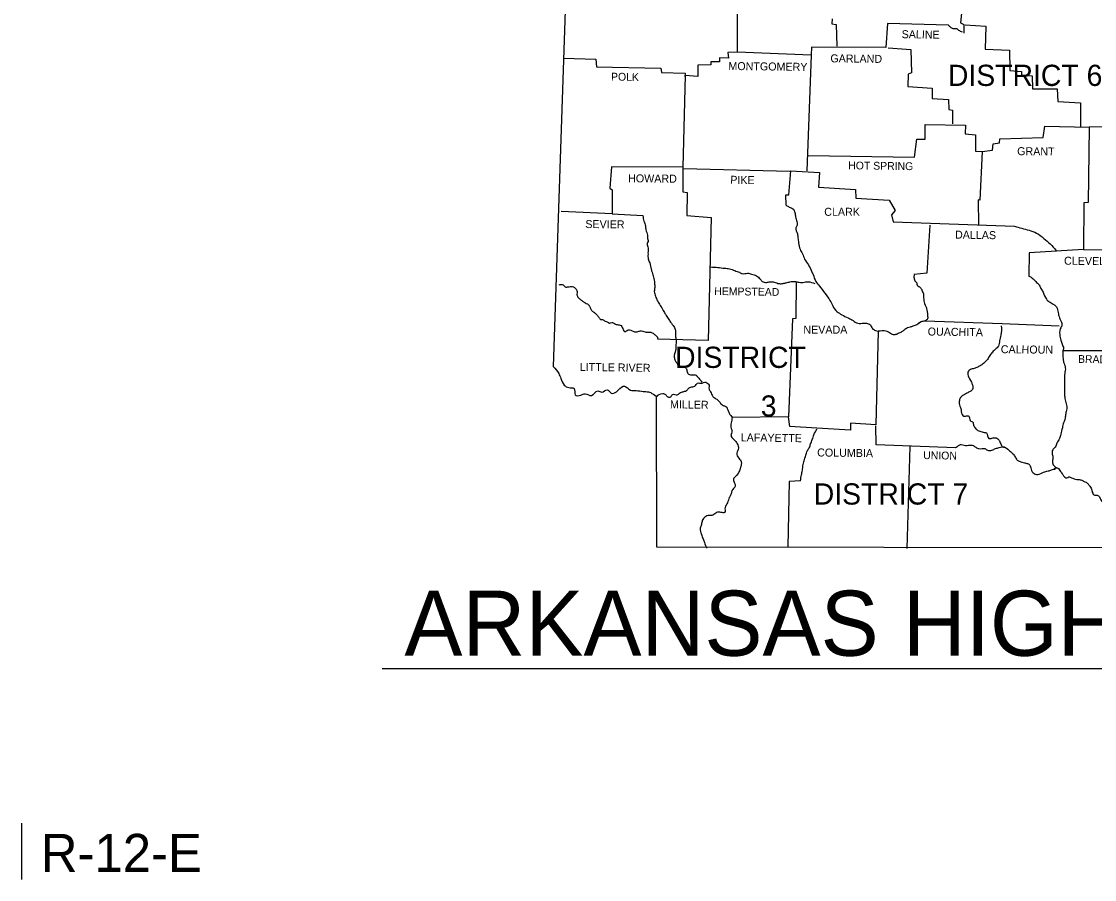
# Model space of a CAD drawing. Extents: x 171 to 3403, y 68 to 2102.
# Drawn here: x 2435 to 3000, y 1174 to 1625 of the extents above; entities that cross this region are included whole.
import ezdxf

# ---------------------------------------------------------------- set-up
doc = ezdxf.new("R2010")
doc.units = 0
for name, color, linetype in [('1', 7, 'Continuous'), ('2', 7, 'Continuous'), ('3', 7, 'Continuous'), ('Default', 7, 'Continuous')]:
    doc.layers.add(name, color=color, linetype=linetype)

msp = doc.modelspace()

# ---------------------------------------------------------------- linework, layer by layer
at = {"layer": '1'}
msp.add_line((2625.16, 1284.87), (3289.7, 1284.87), dxfattribs=at)
for points in [[(2703.71, 1871.91), (2723.96, 1709.3), (2715.15, 1443.86)], [(2812.02, 1666.35), (2811.82, 1609.11), (2806.93, 1609.01), (2807.32, 1606.08), (2802.62, 1606.17), (2802.53, 1604.02), (2797.93, 1604.02), (2798.03, 1602.46), (2791.18, 1602.26), (2791.08, 1596.29), (2784.43, 1596.88), (2783.35, 1548.74), (2745.68, 1548.84), (2744.8, 1537.69), (2746.17, 1536.71), (2746.07, 1524.18), (2719.36, 1525.36)], [(2961.91, 1638.27), (2954.86, 1639.05), (2955.16, 1636.41), (2942.34, 1635.92), (2941.95, 1632.1), (2929.91, 1631.42), (2929.23, 1624.57), (2930.99, 1623.69), (2930.99, 1619.19)], [(2861.72, 1626.72), (2861.62, 1624.08), (2863.87, 1623.69), (2864.26, 1612.34)], [(2922.97, 1623.3), (2890.97, 1624.27), (2890.09, 1611.65), (2850.96, 1611.85), (2850.76, 1607.64)], [(2931.68, 1623.59), (2942.63, 1622.9), (2942.24, 1610.67), (2955.06, 1610.19), (2955.26, 1599.52), (2961.32, 1599.03), (2961.32, 1597.17), (2967, 1596.78), (2967.19, 1589.93), (2980.11, 1589.93), (2980.5, 1583.18), (2992.44, 1582.59), (2992.34, 1569.87)], [(2850.76, 1607.64), (2811.82, 1609.11)], [(2891.27, 1611.46), (2903.11, 1610.58), (2903.5, 1598.25), (2901.83, 1597.66), (2901.64, 1591.11), (2914.46, 1590.23), (2914.46, 1584.84), (2922.97, 1584.36), (2923.07, 1578.97), (2925.12, 1578.68), (2925.02, 1571.44)], [(2720.54, 1606.08), (2737.46, 1605.49), (2737.85, 1601.38), (2771.71, 1600.69), (2772.1, 1598.54), (2784.43, 1598.15), (2784.33, 1596.29)], [(2850.76, 1607.64), (2848.51, 1546.69)], [(3109.06, 1581.13), (3072.08, 1582.1), (3071.88, 1570.07), (2997.03, 1569.78)], [(2849.2, 1554.81), (2905.16, 1554.02), (2906.24, 1563.32), (2910.64, 1563.32), (2910.74, 1571.15), (2931.87, 1570.85), (2931.68, 1566.16), (2937.16, 1565.77), (2937.16, 1557.16), (2940.68, 1556.86)], [(2940.68, 1556.86), (2946.16, 1557.64), (2946.55, 1560.97), (2949.78, 1561.56), (2949.97, 1563.52), (2972.77, 1564.2), (2973.65, 1570.17), (2997.03, 1569.78)], [(2997.03, 1569.58), (2996.45, 1530.05), (2994.2, 1529.96), (2993.9, 1505.4)], [(2940.68, 1556.86), (2939.5, 1531.23), (2938.62, 1531.52), (2938.72, 1518.22)], [(2783.35, 1548.74), (2783.35, 1535.73), (2785.5, 1535.34), (2785.31, 1523.2), (2798.22, 1522.23), (2796.66, 1457.55), (2770.04, 1458.24)], [(2783.55, 1548.06), (2839.51, 1546.59)], [(2837.65, 1528.68), (2837.46, 1534.07), (2839.02, 1534.16), (2840, 1546.78), (2855.07, 1545.81), (2854.68, 1538.08), (2874.15, 1537), (2874.24, 1532.3), (2891.85, 1531.23), (2894.89, 1525.94), (2893.03, 1523.6), (2893.91, 1519.98), (2957.7, 1517.63)], [(2746.07, 1524.18), (2762.31, 1523.2)], [(2913.09, 1518.12), (2911.62, 1492.97), (2904.87, 1492.19)], [(2979.81, 1504.52), (2965.33, 1503.64), (2965.24, 1491.41)], [(2993.9, 1505.4), (2979.62, 1504.52)], [(2993.9, 1505.4), (3028.54, 1505.2)], [(2842.84, 1488.47), (2842.64, 1469), (2840.88, 1468.81), (2838.92, 1417.24)], [(2910.64, 1467.83), (2951.15, 1466.36), (2981.18, 1465.19)], [(2885.98, 1462.35), (2884.71, 1413.04), (2871.5, 1413.92), (2871.41, 1410.3), (2853.79, 1411.37)], [(2983.14, 1452.17), (3027.36, 1452.27)], [(2769.26, 1428.1), (2769.46, 1348.95), (3128.04, 1348.36)], [(2853.79, 1411.37), (2839.61, 1412.16), (2838.92, 1417.24), (2809.28, 1416.95)], [(2926.69, 1401.1), (2884.91, 1402.67), (2884.71, 1412.55)], [(2902.72, 1401.78), (2901.15, 1348.07)], [(2845.18, 1383.68), (2839.12, 1383.29), (2838.43, 1348.85)]]:
    msp.add_lwpolyline(points, dxfattribs=at)
for points in [[(2930.31, 1619.68), (2928.45, 1620.65), (2926.98, 1621.53), (2925.41, 1621.44), (2924.14, 1622.22), (2922.97, 1623.3)], [(2837.65, 1528.68), (2839.22, 1527.71), (2841.08, 1526.83), (2842.05, 1525.36), (2842.45, 1523.11), (2843.13, 1520.66), (2843.33, 1518.12), (2842.74, 1516.75), (2843.52, 1513.62), (2843.82, 1511.46), (2844.11, 1508.92), (2844.89, 1505.5), (2846.16, 1503.15), (2847.34, 1500.31), (2849.29, 1497.28), (2850.96, 1493.95), (2851.74, 1492.19), (2853.21, 1488.57), (2855.07, 1486.12), (2858, 1482.41), (2860.64, 1478.59), (2862.11, 1475.75), (2864.36, 1472.62), (2866.91, 1471.06), (2870.13, 1469.39), (2872.19, 1468.41), (2874.54, 1466.75), (2877.57, 1466.56), (2879.82, 1466.56), (2881.88, 1465.67), (2882.85, 1463.91), (2884.61, 1462.74), (2885.98, 1462.35)], [(2762.31, 1523.2), (2762.8, 1520.27), (2763.68, 1517.73), (2763.78, 1515.77), (2764.66, 1512.83), (2764.66, 1511.76), (2764.96, 1509.61), (2764.56, 1508.43), (2765.05, 1506.08), (2764.96, 1504.32), (2764.96, 1502.85), (2765.05, 1500.41), (2765.84, 1498.26), (2766.62, 1495.03), (2767.11, 1493.36), (2767.89, 1490.82), (2768.38, 1487.69), (2768.48, 1485.34), (2768.28, 1483.19), (2768.87, 1480.74), (2769.95, 1478.3), (2771.32, 1475.95), (2772.98, 1473.31), (2774.15, 1471.25), (2775.62, 1469), (2776.79, 1467.14), (2778.56, 1464.79), (2779.34, 1462.84), (2779.34, 1460.1), (2779.73, 1457.55), (2779.63, 1454.72), (2779.44, 1452.17), (2778.75, 1448.65), (2779.24, 1446.99), (2781.1, 1444.54), (2782.27, 1443.86), (2784.33, 1443.46), (2785.31, 1442.09), (2785.89, 1440.04), (2787.95, 1439.36), (2790.2, 1439.16), (2791.27, 1437.99), (2792.74, 1436.42), (2793.23, 1435.64)], [(2957.7, 1517.63), (2965.33, 1515.48), (2969.25, 1514.01), (2973.16, 1511.17), (2976.39, 1508.33), (2979.62, 1504.71)], [(2798.03, 1496.2), (2801.74, 1495.91), (2805.17, 1495.52), (2807.81, 1495.22), (2810.55, 1494.24), (2813, 1493.36), (2814.56, 1492.68), (2817.2, 1492.87), (2819.45, 1492.39), (2822, 1491.5), (2823.86, 1489.84), (2825.03, 1488.57), (2827.28, 1488.08), (2829.14, 1488.37), (2831.39, 1488.18), (2833.93, 1487.4), (2835.99, 1487.49), (2837.65, 1487.88), (2839.61, 1488.37), (2842.05, 1488.57), (2843.91, 1488.18), (2846.36, 1488.08), (2849.2, 1488.37), (2852.72, 1487.4)], [(2904.87, 1492.19), (2904.87, 1490.33), (2905.55, 1488.57), (2906.24, 1487.79), (2906.53, 1486.51), (2907.41, 1485.93), (2908.68, 1484.75), (2909.37, 1483.09), (2909.86, 1482.01), (2909.86, 1480.64), (2909.96, 1479.27), (2910.15, 1477.61), (2911.33, 1474.68), (2911.62, 1473.5), (2911.81, 1472.52), (2911.91, 1470.86), (2911.91, 1468.9), (2910.64, 1467.83)], [(2965.24, 1491.41), (2967.49, 1489.94), (2969.34, 1487.98), (2970.71, 1486.51), (2971.59, 1484.85), (2972.77, 1482.89), (2974.43, 1479.18), (2975.9, 1477.9), (2977.95, 1476.63), (2979.23, 1475.75), (2980.5, 1472.91), (2981.09, 1470.08), (2982.16, 1467.53), (2982.65, 1465.58), (2981.77, 1463.62), (2981.57, 1459.71), (2982.16, 1457.06), (2982.94, 1455.11), (2983.43, 1452.86), (2983.14, 1452.17)], [(2718.19, 1486.71), (2720.34, 1486.81), (2721.81, 1485.54), (2722.69, 1485.63), (2724.25, 1485.83), (2725.72, 1485.73), (2726.8, 1484.85), (2727.68, 1483.29), (2727.58, 1481.82), (2727.68, 1481.23), (2728.36, 1479.96), (2729.54, 1478.98), (2730.81, 1478), (2731.98, 1477.22), (2733.94, 1475.95), (2734.14, 1475.56), (2734.92, 1473.99), (2735.9, 1472.72), (2737.07, 1471.94), (2738.34, 1470.57), (2738.93, 1469.98), (2739.91, 1468.61), (2740.98, 1468.51), (2742.45, 1467.63), (2743.53, 1467.34), (2744.7, 1466.56), (2745.88, 1466.95), (2747.34, 1466.36), (2749.3, 1465.77), (2750.38, 1465.58), (2751.65, 1463.72), (2752.92, 1462.15), (2754.49, 1463.03), (2757.42, 1462.15), (2759.28, 1462.05), (2760.94, 1462.54), (2762.22, 1462.45), (2764.56, 1461.86), (2766.03, 1461.86), (2767.6, 1461.27), (2769.06, 1460.1), (2770.04, 1458.83), (2770.04, 1458.24)], [(2908.78, 1467.44), (2906.24, 1465.77), (2904.28, 1464.99), (2902.81, 1464.5), (2901.44, 1464.11), (2899.68, 1462.94), (2898.31, 1461.96), (2896.45, 1461.08), (2894.69, 1460.49), (2892.54, 1461.17), (2891.37, 1461.86), (2890.09, 1462.35), (2885.98, 1462.35)], [(2906.24, 1465.77), (2908.78, 1467.44), (2910.64, 1467.83)], [(2950.75, 1465.19), (2950.56, 1460.29), (2949.87, 1457.26), (2949.19, 1454.52), (2947.72, 1452.96), (2946.16, 1451.39), (2944.69, 1449.63), (2943.42, 1447.48), (2942.14, 1446.11), (2940.48, 1444.74), (2938.82, 1443.76), (2936.96, 1442.88), (2934.9, 1442.39), (2933.44, 1441.31), (2933.34, 1438.96), (2935, 1435.64), (2935.59, 1434.07), (2935.79, 1432.21), (2935.1, 1431.14), (2933.53, 1430.26), (2931.68, 1429.18), (2930.01, 1428.2), (2928.84, 1426.54), (2928.64, 1424.29), (2929.43, 1421.65), (2929.72, 1420.08), (2930.99, 1417.63), (2931.97, 1417.73), (2933.73, 1417.63), (2933.93, 1417.15), (2934.02, 1416.66), (2934.42, 1415.38), (2935.88, 1414.31), (2936.08, 1413.33), (2936.96, 1411.47), (2938.43, 1410.2), (2939.5, 1409.81), (2941.75, 1409.12), (2942.93, 1408.83), (2944.2, 1405.99), (2945.77, 1406.09), (2946.94, 1406.29), (2948.9, 1405.8), (2949.78, 1404.62), (2950.66, 1402.67), (2951.83, 1401.3), (2952.61, 1401.3)], [(2983.14, 1452.17), (2983.53, 1446.11), (2984.41, 1443.17), (2984.12, 1440.04), (2984.02, 1437.01), (2984.02, 1434.27), (2984.02, 1431.63), (2984.02, 1428.89), (2984.22, 1426.93), (2984.9, 1424.09), (2985.19, 1421.45), (2984.61, 1418.91), (2984.31, 1416.56), (2983.53, 1414.21), (2982.85, 1411.57), (2982.06, 1408.14), (2981.38, 1405.89), (2980.01, 1403.55), (2979.13, 1401.39), (2977.76, 1400.02), (2977.56, 1397.68), (2977.86, 1395.52), (2977.66, 1393.57), (2978.35, 1391.71), (2980.11, 1390.44)], [(2715.15, 1443.86), (2717.99, 1440.14), (2719.17, 1437.5), (2720.83, 1434.07), (2723.28, 1432.7), (2726.11, 1432.21), (2726.7, 1428.89), (2729.63, 1428.79), (2731.98, 1429.47), (2735.21, 1428.59), (2738.64, 1430.94), (2740.59, 1430.35), (2743.43, 1431.53), (2745.58, 1429.77), (2749.3, 1431.33), (2752.63, 1433.48), (2755.76, 1431.43), (2758.79, 1431.14), (2762.41, 1430.65), (2765.25, 1430.45), (2767.79, 1429.18), (2769.65, 1427.91), (2769.26, 1428.1)], [(2769.26, 1428.1), (2772.68, 1429.57), (2774.15, 1429.08), (2775.42, 1427.81), (2776.89, 1427.81), (2777.67, 1428.98), (2779.14, 1429.08), (2780.32, 1428.98), (2781.59, 1429.77), (2782.66, 1430.26), (2784.13, 1430.75), (2785.21, 1431.14), (2786.19, 1432.21), (2787.95, 1433.09), (2790, 1433.78), (2790.59, 1434.76), (2791.57, 1435.15), (2793.52, 1435.05), (2794.8, 1435.64), (2795.87, 1435.15), (2796.85, 1434.46), (2797.05, 1431.92), (2797.83, 1430.55), (2799, 1428.1), (2800.67, 1426.83), (2802.23, 1425.56), (2802.82, 1424.78), (2804.48, 1423.31), (2805.95, 1422.82), (2806.64, 1421.74), (2807.71, 1419.2), (2809.28, 1416.95)], [(2809.28, 1416.95), (2808.69, 1414.11), (2808.59, 1411.86), (2809.08, 1409.22), (2808.59, 1407.95), (2809.38, 1406.09), (2810.84, 1404.62), (2811.92, 1403.06), (2812.6, 1400.81), (2811.72, 1398.26), (2812.7, 1395.62), (2813.58, 1394.64), (2814.07, 1393.08), (2813.39, 1390.04), (2812.51, 1387.79), (2810.55, 1385.54), (2809.96, 1384.47), (2810.26, 1383), (2810.74, 1380.65), (2810.26, 1379.97), (2808.98, 1378.3), (2808.59, 1376.44), (2807.71, 1374.88), (2806.73, 1372.04), (2805.46, 1369.69), (2805.27, 1367.05), (2803.31, 1367.05), (2801.06, 1367.05), (2799, 1365.58), (2797.15, 1365.49), (2794.89, 1364.61), (2793.52, 1362.75), (2793.04, 1360.69), (2792.45, 1358.73), (2793.04, 1355.41), (2793.92, 1353.06), (2794.6, 1351.2), (2795.78, 1348.17)], [(2845.18, 1383.68), (2845.67, 1386.81), (2846.16, 1389.26), (2846.46, 1391.61), (2847.04, 1394.25), (2847.92, 1397.09), (2848.71, 1399.44), (2849.78, 1401.1), (2850.47, 1403.06), (2851.35, 1405.4), (2852.23, 1407.85), (2853.79, 1410.98)], [(2926.69, 1401.1), (2928.25, 1402.18), (2929.72, 1402.76), (2931.19, 1402.47), (2932.75, 1402.27), (2934.12, 1402.47), (2935.88, 1402.18), (2937.35, 1401.3), (2939.01, 1400.61), (2940.68, 1400.61), (2942.14, 1400.61), (2943.42, 1399.73), (2945.77, 1399.83), (2947.72, 1400.61), (2949.68, 1401.2), (2952.32, 1401.49), (2954.67, 1399.83), (2956.33, 1398.46), (2957.7, 1396.89), (2958.68, 1395.13), (2959.76, 1394.15), (2961.52, 1393.47), (2962.89, 1393.17), (2964.55, 1392.69), (2965.43, 1392.29), (2966.21, 1390.44), (2967.49, 1387.89), (2969.93, 1387.01), (2972.96, 1388.18), (2975.41, 1388.87), (2977.17, 1389.46), (2978.25, 1389.85), (2979.23, 1389.95), (2978.93, 1390.14), (2980.11, 1390.44), (2981.18, 1389.65), (2981.87, 1388.58), (2983.04, 1387.01), (2984.12, 1385.64), (2985.19, 1385.15), (2986.27, 1385.74), (2987.74, 1385.25), (2989.01, 1384.76), (2990.48, 1384.37), (2991.75, 1384.27), (2993.41, 1383.88), (2994.69, 1383.19), (2995.86, 1382.51), (2997.03, 1381.24), (2998.21, 1379.28), (2998.6, 1377.72), (2999.97, 1376.15), (3001.24, 1376.15), (3003.1, 1373.61), (3003.78, 1372.63), (3005.25, 1370.87), (3006.33, 1370.87), (3008.38, 1370.48)]]:
    msp.add_spline(points, degree=3, dxfattribs=at)
at = {"layer": 'Default'}
msp.add_line((2435.48, 1203.63), (2435.48, 1173.89), dxfattribs=at)

# ---------------------------------------------------------------- texts
at = {"layer": '2'}
for s, height, rotation, p in [('SALINE', 4.207, 359.1491, (2898.31, 1616.54)), ('MONTGOMERY', 4.207, 359.2944, (2807.22, 1599.81)), ('GARLAND', 4.207, 359.3658, (2860.84, 1603.83)), ('POLK', 4.108, 359.2152, (2745.49, 1594.24)), ('GRANT', 4.207, 359.4032, (2959.07, 1555)), ('HOT SPRING', 4.109, 359.2216, (2870.23, 1547.57)), ('HOWARD', 4.207, 359.5145, (2754.49, 1540.72)), ('PIKE', 4.206, 359.0452, (2808.2, 1539.94)), ('SEVIER', 4.207, 359.4271, (2731.98, 1516.65)), ('DALLAS', 4.206, 359.2462, (2926.39, 1511.07)), ('CLEVELAND', 4.207, 359.3377, (2983.73, 1497.37)), ('HEMPSTEAD', 4.108, 359.1885, (2799.79, 1481.43)), ('OUACHITA', 4.207, 359.2043, (2912.01, 1460.1)), ('CALHOUN', 4.207, 359.3634, (2950.46, 1450.8)), ('LITTLE RIVER', 4.2073, 359.1697, (2729.05, 1441.51)), ('BRADLEY', 4.108, 359.1449, (2991.07, 1445.72)), ('MILLER', 4.206, 359.1319, (2776.5, 1421.84)), ('LAFAYETTE', 4.206, 359.1839, (2813.68, 1404.43)), ('COLUMBIA', 4.206, 359.2125, (2853.89, 1396.5)), ('UNION', 4.109, 358.9584, (2909.66, 1395.13))]:
    msp.add_text(s, height=height, rotation=rotation, dxfattribs=at).set_placement(p)
for s, height, p in [('CLARK', 4.207, (2857.63, 1523.08)), ('NEVADA', 4.207, (2846.65, 1461.08)), ('ARKANSAS HIGHWAY DISTRICT 10', 34.244, (2636.86, 1291.62))]:
    msp.add_text(s, height=height, dxfattribs=at).set_placement(p)
at = {"layer": '3'}
for s, height, p in [('DISTRICT 6', 11.154, (2922.67, 1591.4)), ('DISTRICT', 11.154, (2779.19, 1443.06)), ('3', 11.06, (2824.3, 1417.53)), ('DISTRICT 7', 11.154, (2852.13, 1371.16))]:
    msp.add_text(s, height=height, dxfattribs=at).set_placement(p)
at = {"layer": 'Default'}
msp.add_text('R-12-E', height=20, dxfattribs=at).set_placement((2445.66, 1177.92))

doc.saveas('drawing.dxf')
